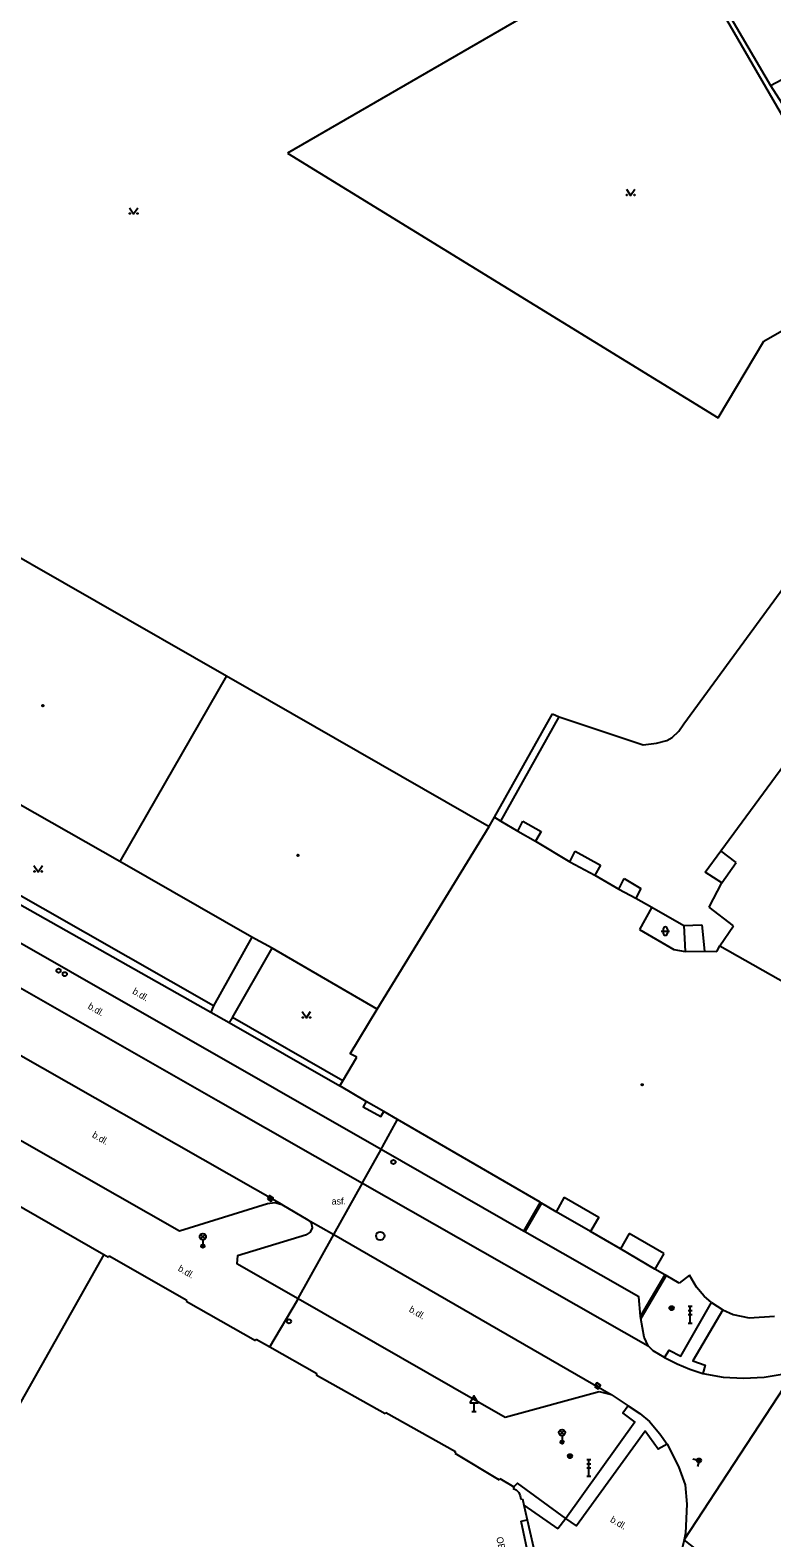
# Model space of a CAD drawing. Extents: x -599770 to -598493, y -1162076 to -1159209.
# Drawn here: x -599118.7 to -599074.3, y -1159605.2 to -1159515 of the extents above; entities that cross this region are included whole.
import ezdxf

# ---------------------------------------------------------------- set-up
doc = ezdxf.new("R2010")
doc.units = 0
doc.layers.add('Podklad', color=7, linetype='Continuous')

msp = doc.modelspace()

# ---------------------------------------------------------------- linework, layer by layer
at = {"layer": 'Podklad'}
for p, q in [((-599080.903, -1159568.918), (-599080.403, -1159568.918)), ((-599080.778, -1159568.793), (-599080.778, -1159569.043)), ((-599080.528, -1159568.793), (-599080.528, -1159569.043)), ((-599104.385, -1159584.833), (-599104.175, -1159584.967)), ((-599108.453, -1159587.33), (-599108.188, -1159587.065)), ((-599108.453, -1159587.065), (-599108.188, -1159587.33)), ((-599108.32, -1159587.385), (-599108.32, -1159587.76)), ((-599079.295, -1159591.36), (-599079.045, -1159591.36)), ((-599079.17, -1159592.36), (-599079.17, -1159591.36)), ((-599079.295, -1159591.61), (-599079.045, -1159591.61)), ((-599079.295, -1159591.86), (-599079.045, -1159591.86)), ((-599079.295, -1159592.36), (-599079.045, -1159592.36)), ((-599084.815, -1159596.053), (-599084.605, -1159596.187)), ((-599092.225, -1159597.65), (-599091.975, -1159597.65)), ((-599092.1, -1159597.141), (-599092.1, -1159597.65)), ((-599086.962, -1159599.05), (-599086.697, -1159598.785)), ((-599086.962, -1159598.785), (-599086.697, -1159599.05)), ((-599086.83, -1159599.105), (-599086.83, -1159599.48)), ((-599085.355, -1159600.53), (-599085.105, -1159600.53)), ((-599085.23, -1159601.53), (-599085.23, -1159600.53)), ((-599085.355, -1159600.78), (-599085.105, -1159600.78)), ((-599085.355, -1159601.03), (-599085.105, -1159601.03)), ((-599085.355, -1159601.53), (-599085.105, -1159601.53))]:
    msp.add_line(p, q, dxfattribs=at)
for points in [[(-599080.11, -1159508.99), (-599103.25, -1159522.39)], [(-599068.08, -1159529.76), (-599080.11, -1159508.99)], [(-599079.92, -1159508.82), (-599074.36, -1159518.34)], [(-599074.36, -1159518.34), (-599073.68, -1159517.97)], [(-599074.36, -1159518.34), (-599073.33, -1159519.96)], [(-599103.25, -1159522.39), (-599077.49, -1159538.21)], [(-599082.98, -1159524.535), (-599082.73, -1159524.91), (-599082.48, -1159524.535)], [(-599112.71, -1159525.645), (-599112.46, -1159526.02), (-599112.21, -1159525.645)], [(-599196.77, -1159528.01), (-599168.3, -1159544.27), (-599141.084, -1159559.839), (-599133.11, -1159564.4), (-599107.4, -1159579.07), (-599098.775, -1159583.988), (-599081.69, -1159593.73)], [(-599074.76, -1159533.63), (-599068.45, -1159530)], [(-599077.49, -1159538.21), (-599074.76, -1159533.63)], [(-599079.54, -1159556.52), (-599065.84, -1159537.79)], [(-599122.51, -1159544.72), (-599106.91, -1159553.65)], [(-599077.34, -1159564.12), (-599068.46, -1159552.05)], [(-599106.91, -1159553.65), (-599113.29, -1159564.75)], [(-599106.91, -1159553.65), (-599091.19, -1159562.66)], [(-599089.13, -1159586.86), (-599097.662, -1159581.983), (-599141.089, -1159557.161), (-599144.24, -1159555.36)], [(-599113.29, -1159564.75), (-599128.55, -1159556.08)], [(-599090.88, -1159562.11), (-599087.41, -1159555.92)], [(-599090.5, -1159562.34), (-599087, -1159556.09)], [(-599087.41, -1159555.92), (-599087, -1159556.09)], [(-599087, -1159556.09), (-599081.98, -1159557.77)], [(-599080.24, -1159557.34), (-599079.84, -1159556.95)], [(-599079.84, -1159556.95), (-599079.54, -1159556.52)], [(-599081.98, -1159557.77), (-599081.19, -1159557.68)], [(-599081.19, -1159557.68), (-599080.57, -1159557.52)], [(-599080.57, -1159557.52), (-599080.24, -1159557.34)], [(-599131.5, -1159560.43), (-599107.85, -1159573.76)], [(-599107.68, -1159573.39), (-599130.81, -1159560.21)], [(-599091.19, -1159562.66), (-599090.88, -1159562.11)], [(-599090.88, -1159562.11), (-599090.5, -1159562.34)], [(-599090.5, -1159562.34), (-599089.47, -1159562.94)], [(-599089.47, -1159562.94), (-599089.17, -1159562.35)], [(-599089.17, -1159562.35), (-599088.08, -1159562.95)], [(-599097.9, -1159573.58), (-599091.19, -1159562.66)], [(-599089.47, -1159562.94), (-599088.42, -1159563.53)], [(-599088.08, -1159562.95), (-599088.42, -1159563.53)], [(-599088.42, -1159563.53), (-599086.37, -1159564.77)], [(-599086.37, -1159564.77), (-599086.05, -1159564.14)], [(-599086.05, -1159564.14), (-599084.53, -1159564.98)], [(-599078.27, -1159565.39), (-599077.34, -1159564.12)], [(-599076.42, -1159564.82), (-599077.34, -1159564.12)], [(-599118.42, -1159564.995), (-599118.17, -1159565.37), (-599117.92, -1159564.995)], [(-599105.39, -1159569.28), (-599113.29, -1159564.75)], [(-599086.37, -1159564.77), (-599084.88, -1159565.58)], [(-599084.53, -1159564.98), (-599084.88, -1159565.58)], [(-599077.27, -1159566.03), (-599076.42, -1159564.82)], [(-599084.88, -1159565.58), (-599083.43, -1159566.4)], [(-599083.43, -1159566.4), (-599083.12, -1159565.78)], [(-599083.12, -1159565.78), (-599082.11, -1159566.37)], [(-599077.27, -1159566.03), (-599078.27, -1159565.39)], [(-599078.04, -1159567.49), (-599077.27, -1159566.03)], [(-599083.43, -1159566.4), (-599082.42, -1159566.95)], [(-599082.11, -1159566.37), (-599082.42, -1159566.95)], [(-599082.42, -1159566.95), (-599081.47, -1159567.49)], [(-599081.47, -1159567.49), (-599082.2, -1159568.83)], [(-599081.47, -1159567.49), (-599079.54, -1159568.59)], [(-599076.57, -1159568.6), (-599078.04, -1159567.49)], [(-599082.2, -1159568.83), (-599080.15, -1159570.02)], [(-599079.54, -1159568.59), (-599078.47, -1159568.55)], [(-599079.54, -1159568.59), (-599079.46, -1159570.13)], [(-599078.47, -1159568.55), (-599078.32, -1159570.12)], [(-599077.39, -1159569.8), (-599076.57, -1159568.6)], [(-599105.39, -1159569.28), (-599107.68, -1159573.39)], [(-599104.18, -1159569.93), (-599105.39, -1159569.28)], [(-599077.57, -1159570.13), (-599077.39, -1159569.8)], [(-599077.39, -1159569.8), (-599062.7, -1159578.11)], [(-599106.55, -1159574.08), (-599104.18, -1159569.93)], [(-599097.9, -1159573.58), (-599104.18, -1159569.93)], [(-599080.15, -1159570.02), (-599079.46, -1159570.13)], [(-599079.46, -1159570.13), (-599078.32, -1159570.12)], [(-599078.32, -1159570.12), (-599077.57, -1159570.13)], [(-599107.68, -1159573.39), (-599107.85, -1159573.76)], [(-599107.85, -1159573.76), (-599106.74, -1159574.39)], [(-599106.74, -1159574.39), (-599106.55, -1159574.08)], [(-599099.95, -1159577.87), (-599106.55, -1159574.08)], [(-599102.37, -1159573.735), (-599102.12, -1159574.11), (-599101.87, -1159573.735)], [(-599099.51, -1159576.26), (-599097.9, -1159573.58)], [(-599122.65, -1159574.43), (-599122.46, -1159574.63), (-599122.41, -1159574.91), (-599122.52, -1159575.16), (-599122.75, -1159575.32), (-599126.5, -1159576.43), (-599126.7, -1159577.18), (-599109.71, -1159586.85), (-599104.45, -1159585.21), (-599104.01, -1159585.16), (-599103.59, -1159585.28)], [(-599103.59, -1159585.28), (-599122.65, -1159574.43)], [(-599106.74, -1159574.39), (-599100.13, -1159578.18)], [(-599099.95, -1159577.87), (-599099.1, -1159576.45)], [(-599099.1, -1159576.45), (-599099.51, -1159576.26)], [(-599100.13, -1159578.18), (-599099.95, -1159577.87)], [(-599098.55, -1159579.1), (-599100.13, -1159578.18)], [(-599098.55, -1159579.1), (-599098.73, -1159579.42), (-599097.68, -1159580.01), (-599097.5, -1159579.7)], [(-599097.5, -1159579.7), (-599098.55, -1159579.1)], [(-599088.14, -1159585.14), (-599096.667, -1159580.19), (-599097.5, -1159579.7)], [(-599097.576, -1159581.829), (-599096.667, -1159580.19)], [(-599125.42, -1159581.84), (-599114.25, -1159588.26)], [(-599100.587, -1159587.253), (-599100.486, -1159587.07), (-599098.775, -1159583.988), (-599098.747, -1159583.937), (-599097.662, -1159581.983), (-599097.576, -1159581.829)], [(-599088.14, -1159585.14), (-599089.13, -1159586.86)], [(-599088.06, -1159585.19), (-599089.05, -1159586.9)], [(-599088.06, -1159585.19), (-599088.14, -1159585.14)], [(-599080.69, -1159589.47), (-599081.28, -1159589.13), (-599083.34, -1159587.93), (-599085.13, -1159586.89), (-599087.19, -1159585.7), (-599088.06, -1159585.19)], [(-599086.7, -1159584.84), (-599087.19, -1159585.7)], [(-599086.7, -1159584.84), (-599084.64, -1159586.02)], [(-599103.59, -1159585.28), (-599102.03, -1159586.18)], [(-599084.64, -1159586.02), (-599085.13, -1159586.89)], [(-599102.12, -1159587.09), (-599101.88, -1159586.93), (-599101.77, -1159586.67), (-599101.83, -1159586.38), (-599102.03, -1159586.18)], [(-599102.03, -1159586.18), (-599100.49, -1159587.07), (-599083.9, -1159596.63)], [(-599089.05, -1159586.9), (-599089.13, -1159586.86)], [(-599082.13, -1159591.94), (-599082.23, -1159590.8), (-599089.05, -1159586.9)], [(-599102.12, -1159587.09), (-599106.25, -1159588.34), (-599106.28, -1159588.8), (-599102.613, -1159590.902), (-599090.23, -1159598), (-599084.62, -1159596.46)], [(-599104.322, -1159593.788), (-599102.665, -1159590.995), (-599102.613, -1159590.902), (-599100.587, -1159587.253)], [(-599082.81, -1159587.01), (-599083.34, -1159587.93)], [(-599080.75, -1159588.21), (-599082.81, -1159587.01)], [(-599114.25, -1159588.26), (-599120.92, -1159600.09)], [(-599114.25, -1159588.26), (-599113.97, -1159588.42)], [(-599113.97, -1159588.42), (-599113.93, -1159588.35)], [(-599113.93, -1159588.35), (-599109.27, -1159590.99)], [(-599080.75, -1159588.21), (-599081.28, -1159589.13)], [(-599080.69, -1159589.47), (-599082.13, -1159591.94)], [(-599080.6, -1159589.52), (-599082.11, -1159592.09)], [(-599080.6, -1159589.52), (-599080.69, -1159589.47)], [(-599079.83, -1159589.97), (-599080.6, -1159589.52)], [(-599079.2, -1159589.5), (-599079.83, -1159589.97)], [(-599078.79, -1159590.22), (-599079.2, -1159589.5)], [(-599078.33, -1159590.75), (-599078.79, -1159590.22)], [(-599109.27, -1159590.99), (-599109.31, -1159591.06)], [(-599109.31, -1159591.06), (-599105.17, -1159593.4)], [(-599080.7, -1159594.42), (-599080.43, -1159593.98), (-599079.72, -1159594.34), (-599077.89, -1159591.14)], [(-599078.41, -1159595.38), (-599077.2, -1159595.59), (-599075.98, -1159595.66), (-599074.75, -1159595.59), (-599073.54, -1159595.39), (-599072.79, -1159595.04), (-599071.98, -1159594.66), (-599070.82, -1159593.92), (-599070.05, -1159593.27), (-599069.32, -1159592.5), (-599068.29, -1159591.12)], [(-599077.89, -1159591.14), (-599078.33, -1159590.75)], [(-599077.89, -1159591.14), (-599077.22, -1159591.58)], [(-599082.11, -1159592.09), (-599082.13, -1159591.94)], [(-599081.69, -1159593.73), (-599081.93, -1159593.21), (-599082.11, -1159592.09)], [(-599077.22, -1159591.58), (-599079, -1159594.63), (-599078.27, -1159594.88), (-599078.41, -1159595.38)], [(-599077.22, -1159591.58), (-599076.59, -1159591.85)], [(-599076.59, -1159591.85), (-599075.64, -1159592.05)], [(-599075.64, -1159592.05), (-599074.12, -1159591.95)], [(-599053.95, -1159592.9), (-599062.47, -1159605.75), (-599068.16, -1159614.32), (-599073.15, -1159610.38), (-599079.53, -1159605.33), (-599072.79, -1159595.04)], [(-599105.17, -1159593.4), (-599105.13, -1159593.33)], [(-599105.13, -1159593.33), (-599104.322, -1159593.788), (-599101.51, -1159595.38)], [(-599080.7, -1159594.42), (-599081.38, -1159594.02), (-599081.69, -1159593.73)], [(-599080.7, -1159594.42), (-599079.94, -1159594.8), (-599079.19, -1159595.12), (-599078.41, -1159595.38)], [(-599101.51, -1159595.38), (-599101.55, -1159595.45)], [(-599101.55, -1159595.45), (-599097.42, -1159597.78)], [(-599084.62, -1159596.46), (-599083.9, -1159596.63)], [(-599083.9, -1159596.63), (-599082.87, -1159597.32)], [(-599097.42, -1159597.78), (-599097.38, -1159597.71)], [(-599097.38, -1159597.71), (-599093.2, -1159600.05)], [(-599082.87, -1159597.32), (-599083.19, -1159597.76), (-599082.48, -1159598.3), (-599086.6, -1159604.05)], [(-599082.87, -1159597.32), (-599082.18, -1159597.78), (-599081.6, -1159598.26), (-599080.98, -1159598.98), (-599080.55, -1159599.61)], [(-599080.55, -1159599.61), (-599081.08, -1159599.91), (-599081.87, -1159598.83), (-599085.97, -1159604.49), (-599086.6, -1159604.05)], [(-599080.55, -1159599.61), (-599079.86, -1159600.95), (-599079.47, -1159602.04), (-599079.36, -1159603.19), (-599079.44, -1159604.94), (-599079.53, -1159605.33), (-599079.85, -1159606.64), (-599080.55, -1159608.24), (-599081.54, -1159609.68)], [(-599093.2, -1159600.05), (-599093.25, -1159600.14)], [(-599093.25, -1159600.14), (-599090.6, -1159601.74)], [(-599079.005, -1159600.493), (-599078.64, -1159600.58), (-599078.727, -1159600.945)], [(-599090.6, -1159601.74), (-599090.55, -1159601.66)], [(-599090.55, -1159601.66), (-599089.71, -1159602.16)], [(-599089.71, -1159602.16), (-599089.76, -1159602.25)], [(-599089.76, -1159602.25), (-599089.57, -1159602.34)], [(-599086.6, -1159604.05), (-599089.5, -1159601.94), (-599089.71, -1159602.16)], [(-599089.57, -1159602.34), (-599089.42, -1159602.5)], [(-599089.42, -1159602.5), (-599089.33, -1159602.69)], [(-599089.33, -1159602.69), (-599089.3, -1159602.9)], [(-599089.3, -1159602.9), (-599089.2, -1159602.88)], [(-599089.2, -1159602.88), (-599089.116, -1159603.257), (-599088.92, -1159604.14), (-599088.39, -1159606.49), (-599087.32, -1159611.28)], [(-599089.27, -1159604.21), (-599088.92, -1159604.14)], [(-599089.116, -1159603.257), (-599087.08, -1159604.68)], [(-599086.6, -1159604.05), (-599087.08, -1159604.68)], [(-599088.78, -1159606.57), (-599089.27, -1159604.21)]]:
    msp.add_lwpolyline(points, dxfattribs=at)
for points in [[(-599104.453, -1159584.938), (-599104.242, -1159585.073), (-599104.107, -1159584.862), (-599104.318, -1159584.727)], [(-599084.883, -1159596.158), (-599084.672, -1159596.293), (-599084.537, -1159596.082), (-599084.748, -1159595.947)], [(-599092.35, -1159597.141), (-599091.85, -1159597.141), (-599092.1, -1159596.708)]]:
    msp.add_lwpolyline(points, close=True, dxfattribs=at)
for centre, radius in [((-599082.955, -1159524.885), 0.025), ((-599082.505, -1159524.885), 0.025), ((-599112.685, -1159525.995), 0.025), ((-599112.235, -1159525.995), 0.025), ((-599117.89, -1159555.43), 0.045), ((-599117.89, -1159555.43), 0.0199), ((-599102.63, -1159564.38), 0.045), ((-599102.63, -1159564.38), 0.0199), ((-599118.395, -1159565.345), 0.025), ((-599117.945, -1159565.345), 0.025), ((-599116.95, -1159571.28), 0.125), ((-599116.58, -1159571.49), 0.125), ((-599102.345, -1159574.085), 0.025), ((-599101.895, -1159574.085), 0.025), ((-599082.04, -1159578.11), 0.045), ((-599082.04, -1159578.11), 0.0199), ((-599096.92, -1159582.73), 0.125), ((-599097.71, -1159587.15), 0.25), ((-599108.32, -1159587.198), 0.188), ((-599108.32, -1159587.76), 0.1), ((-599108.32, -1159587.76), 0.0723), ((-599108.32, -1159587.76), 0.0438), ((-599080.28, -1159591.47), 0.125), ((-599080.28, -1159591.47), 0.1), ((-599080.28, -1159591.47), 0.075), ((-599080.28, -1159591.47), 0.05), ((-599080.28, -1159591.47), 0.025), ((-599103.17, -1159592.26), 0.125), ((-599086.83, -1159598.918), 0.188), ((-599086.83, -1159599.48), 0.1), ((-599086.83, -1159599.48), 0.0723), ((-599086.83, -1159599.48), 0.0438), ((-599086.36, -1159600.32), 0.125), ((-599086.36, -1159600.32), 0.1), ((-599086.36, -1159600.32), 0.075), ((-599086.36, -1159600.32), 0.05), ((-599086.36, -1159600.32), 0.025), ((-599078.64, -1159600.58), 0.125), ((-599078.64, -1159600.58), 0.09), ((-599078.64, -1159600.58), 0.055)]:
    msp.add_circle(centre, radius, dxfattribs=at)
for centre, start, end in [((-599080.653, -1159568.793), 0, 180), ((-599080.653, -1159569.043), 180, 0)]:
    msp.add_arc(centre, 0.125, start, end, dxfattribs=at)

# ---------------------------------------------------------------- texts
for s, rotation, p in [('b.dl.', 329.62, (-599112.57, -1159572.63)), ('b.dl.', 329.62, (-599115.24, -1159573.52)), ('b.dl.', 329.62, (-599114.98, -1159581.22)), ('b.dl.', 329.62, (-599109.85, -1159589.21)), ('b.dl.', 329.62, (-599096.03, -1159591.66)), ('b.dl.', 329.62, (-599083.99, -1159604.23)), ('OBCHOD', 281.72, (-599090.77, -1159605.19))]:
    msp.add_text(s, height=0.4, rotation=rotation, dxfattribs=at).set_placement(p)
msp.add_text('asf.', height=0.4, dxfattribs=at).set_placement((-599100.62, -1159585.27))

doc.saveas('drawing.dxf')
